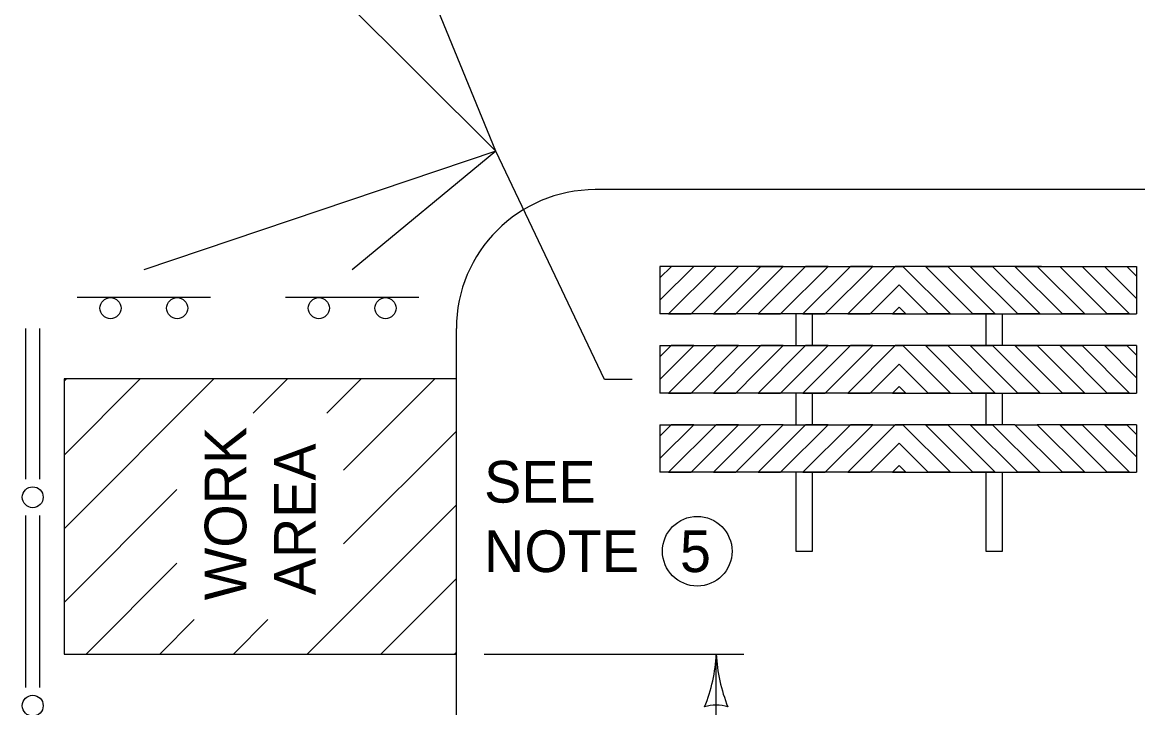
# Model space of a CAD drawing. Extents: x 49991.4 to 50021, y 49987.6 to 50011.4.
# Drawn here: x 50010.578 to 50012.184, y 49992.395 to 49993.381 of the extents above; entities that cross this region are included whole.
import ezdxf

# ---------------------------------------------------------------- set-up
doc = ezdxf.new("R2010")
doc.units = 0
for name, color, linetype in [('Level 1', 7, 'Continuous'), ('Level 2', 7, 'Continuous'), ('Level 3', 7, 'Continuous')]:
    doc.layers.add(name, color=color, linetype=linetype)

# ---------------------------------------------------------------- blocks, each defined once
blk = doc.blocks.new('ARR')
at = {"layer": 'Level 3'}
for centre, radius, start, end in [((1.53, 37.02), 37.05, 247.456, 267.6395), ((-21.37, 0), 9.13, 342.1388, 17.8612), ((1.92, -38.79), 38.83, 92.8273, 112.0772)]:
    blk.add_arc(centre, radius, start, end, dxfattribs=at)

msp = doc.modelspace()

# ---------------------------------------------------------------- linework, layer by layer
at = {"layer": 'Level 1'}
for p, q in [((50013.2032, 49993.1404), (50011.4032, 49993.1404)), ((50011.6213, 49993.03), (50011.4963, 49993.03)), ((50011.4963, 49992.9812), (50011.5451, 49993.03)), ((50011.4963, 49993.0134), (50011.5129, 49993.03)), ((50011.4963, 49993.03), (50011.4963, 49992.9616)), ((50011.5089, 49992.9616), (50011.5773, 49993.03)), ((50011.5411, 49992.9616), (50011.6095, 49993.03)), ((50011.5733, 49992.9616), (50011.6417, 49993.03)), ((50011.6417, 49993.03), (50011.6018, 49993.03)), ((50011.6055, 49992.9616), (50011.6739, 49993.03)), ((50011.6356, 49993.03), (50011.8408, 49993.03)), ((50011.6378, 49992.9616), (50011.7062, 49993.03)), ((50011.7062, 49993.03), (50011.6378, 49992.9616)), ((50011.67, 49992.9616), (50011.7384, 49993.03)), ((50011.67, 49992.9616), (50011.7384, 49993.03)), ((50011.7022, 49992.9616), (50011.7706, 49993.03)), ((50011.7706, 49993.03), (50011.7022, 49992.9616)), ((50011.7345, 49992.9616), (50011.8029, 49993.03)), ((50011.7345, 49992.9616), (50011.8029, 49993.03)), ((50011.7668, 49992.9616), (50011.8352, 49993.03)), ((50011.8352, 49993.03), (50011.7668, 49992.9616)), ((50011.8408, 49993.03), (50011.8352, 49993.03)), ((50012.046, 49993.03), (50011.8408, 49993.03)), ((50011.8408, 49993.03), (50011.8463, 49993.03)), ((50011.8463, 49993.03), (50011.9147, 49992.9616)), ((50011.9147, 49992.9616), (50011.8463, 49993.03)), ((50011.947, 49992.9616), (50011.8786, 49993.03)), ((50011.947, 49992.9616), (50011.8786, 49993.03)), ((50011.9793, 49992.9616), (50011.9109, 49993.03)), ((50011.9109, 49993.03), (50011.9793, 49992.9616)), ((50012.0115, 49992.9616), (50011.9431, 49993.03)), ((50012.0115, 49992.9616), (50011.9431, 49993.03)), ((50012.0437, 49992.9616), (50011.9753, 49993.03)), ((50011.9753, 49993.03), (50012.0437, 49992.9616)), ((50012.076, 49992.9616), (50012.0076, 49993.03)), ((50012.1082, 49992.9616), (50012.0398, 49993.03)), ((50012.0398, 49993.03), (50012.0797, 49993.03)), ((50012.0602, 49993.03), (50012.1828, 49993.03)), ((50012.1404, 49992.9616), (50012.072, 49993.03)), ((50012.1726, 49992.9616), (50012.1042, 49993.03)), ((50012.1828, 49992.9837), (50012.1364, 49993.03)), ((50012.1828, 49993.0159), (50012.1686, 49993.03)), ((50012.1828, 49993.03), (50012.1828, 49992.9616)), ((50011.799, 49992.9616), (50011.8408, 49993.0034)), ((50011.799, 49992.9616), (50011.8408, 49993.0034)), ((50011.8825, 49992.9616), (50011.8408, 49993.0034)), ((50011.8825, 49992.9616), (50011.8408, 49993.0034)), ((50010.7532, 49992.985), (50010.6572, 49992.985)), ((50010.8492, 49992.985), (50010.7532, 49992.985)), ((50011.0532, 49992.985), (50010.9572, 49992.985)), ((50011.1492, 49992.985), (50011.0532, 49992.985)), ((50011.8408, 49992.9616), (50011.6356, 49992.9616)), ((50011.6926, 49992.9161), (50011.6926, 49992.9616)), ((50011.8312, 49992.9616), (50011.8408, 49992.9711)), ((50011.8408, 49992.9711), (50011.8312, 49992.9616)), ((50011.8312, 49992.9616), (50011.8408, 49992.9616)), ((50011.8503, 49992.9616), (50011.8408, 49992.9711)), ((50011.8408, 49992.9711), (50011.8503, 49992.9616)), ((50011.8408, 49992.9616), (50012.046, 49992.9616)), ((50011.8503, 49992.9616), (50011.8408, 49992.9616)), ((50011.9662, 49992.9161), (50011.9662, 49992.9616)), ((50010.5832, 49992.7239), (50010.5832, 49992.9404)), ((50010.6032, 49992.7239), (50010.6032, 49992.9404)), ((50011.2032, 49988.1586), (50011.2032, 49992.9404)), ((50011.4963, 49992.8996), (50011.5127, 49992.9161)), ((50011.4963, 49992.8673), (50011.545, 49992.9161)), ((50011.4963, 49992.9161), (50011.6356, 49992.9161)), ((50011.4963, 49992.9161), (50011.4963, 49992.8477)), ((50011.5088, 49992.8477), (50011.5772, 49992.9161)), ((50011.5411, 49992.8477), (50011.6095, 49992.9161)), ((50011.5733, 49992.8477), (50011.6356, 49992.9099)), ((50011.6356, 49992.8777), (50011.6739, 49992.9161)), ((50011.6356, 49992.9161), (50011.8408, 49992.9161)), ((50011.6378, 49992.8477), (50011.7062, 49992.9161)), ((50011.7062, 49992.9161), (50011.6378, 49992.8477)), ((50011.67, 49992.8477), (50011.7384, 49992.9161)), ((50011.67, 49992.8477), (50011.7384, 49992.9161)), ((50011.7022, 49992.8477), (50011.7706, 49992.9161)), ((50011.7706, 49992.9161), (50011.7022, 49992.8477)), ((50011.7345, 49992.8477), (50011.8029, 49992.9161)), ((50011.7345, 49992.8477), (50011.8029, 49992.9161)), ((50011.7668, 49992.8477), (50011.8352, 49992.9161)), ((50011.8352, 49992.9161), (50011.7668, 49992.8477)), ((50011.8408, 49992.9161), (50011.8352, 49992.9161)), ((50012.046, 49992.9161), (50011.8408, 49992.9161)), ((50011.8408, 49992.9161), (50011.8463, 49992.9161)), ((50011.9147, 49992.8477), (50011.8463, 49992.9161)), ((50011.8463, 49992.9161), (50011.9147, 49992.8477)), ((50011.947, 49992.8477), (50011.8786, 49992.9161)), ((50011.947, 49992.8477), (50011.8786, 49992.9161)), ((50011.9793, 49992.8477), (50011.9109, 49992.9161)), ((50011.9109, 49992.9161), (50011.9793, 49992.8477)), ((50012.0115, 49992.8477), (50011.9431, 49992.9161)), ((50012.0115, 49992.8477), (50011.9431, 49992.9161)), ((50012.0437, 49992.8477), (50011.9753, 49992.9161)), ((50011.9753, 49992.9161), (50012.0437, 49992.8477)), ((50012.046, 49992.8777), (50012.0076, 49992.9161)), ((50012.1828, 49992.9161), (50012.046, 49992.9161)), ((50012.1082, 49992.8477), (50012.046, 49992.9099)), ((50012.1405, 49992.8477), (50012.0721, 49992.9161)), ((50012.1727, 49992.8477), (50012.1043, 49992.9161)), ((50012.1828, 49992.8698), (50012.1365, 49992.9161)), ((50012.1828, 49992.9021), (50012.1688, 49992.9161)), ((50012.1828, 49992.9161), (50012.1828, 49992.8477)), ((50011.6055, 49992.8477), (50011.6356, 49992.8777)), ((50011.799, 49992.8477), (50011.8408, 49992.8894)), ((50011.799, 49992.8477), (50011.8408, 49992.8894)), ((50011.8825, 49992.8477), (50011.8408, 49992.8894)), ((50011.8825, 49992.8477), (50011.8408, 49992.8894)), ((50012.076, 49992.8477), (50012.046, 49992.8777)), ((50011.2032, 49992.868), (50010.6384, 49992.868)), ((50010.6384, 49992.868), (50010.6384, 49992.4721)), ((50010.6384, 49992.8646), (50010.6418, 49992.868)), ((50010.6384, 49992.7585), (50010.7478, 49992.868)), ((50010.6384, 49992.6524), (50010.8539, 49992.868)), ((50010.9105, 49992.8185), (50010.96, 49992.868)), ((50011.0165, 49992.8185), (50011.066, 49992.868)), ((50011.0408, 49992.7367), (50011.1721, 49992.868)), ((50011.8408, 49992.8477), (50011.4963, 49992.8477)), ((50011.8312, 49992.8477), (50011.8408, 49992.8572)), ((50011.8408, 49992.8572), (50011.8312, 49992.8477)), ((50011.8312, 49992.8477), (50011.8408, 49992.8477)), ((50011.8503, 49992.8477), (50011.8408, 49992.8572)), ((50011.8408, 49992.8572), (50011.8503, 49992.8477)), ((50011.8408, 49992.8477), (50012.1828, 49992.8477)), ((50011.8503, 49992.8477), (50011.8408, 49992.8477)), ((50011.4963, 49992.7856), (50011.5127, 49992.8021)), ((50011.4963, 49992.7534), (50011.545, 49992.8021)), ((50011.4963, 49992.7534), (50011.545, 49992.8021)), ((50011.5127, 49992.8021), (50011.4963, 49992.7856)), ((50011.4963, 49992.8021), (50011.4963, 49992.7337)), ((50011.5088, 49992.7337), (50011.5772, 49992.8021)), ((50011.5772, 49992.8021), (50011.5088, 49992.7337)), ((50011.5411, 49992.7337), (50011.6095, 49992.8021)), ((50011.5411, 49992.7337), (50011.6095, 49992.8021)), ((50011.5733, 49992.7337), (50011.6417, 49992.8021)), ((50011.6417, 49992.8021), (50011.5733, 49992.7337)), ((50011.6055, 49992.7337), (50011.6739, 49992.8021)), ((50011.6055, 49992.7337), (50011.6739, 49992.8021)), ((50011.6378, 49992.7337), (50011.7062, 49992.8021)), ((50011.7062, 49992.8021), (50011.6378, 49992.7337)), ((50011.67, 49992.7337), (50011.7384, 49992.8021)), ((50011.67, 49992.7337), (50011.7384, 49992.8021)), ((50011.6739, 49992.8021), (50011.8408, 49992.8021)), ((50011.7022, 49992.7337), (50011.7706, 49992.8021)), ((50011.7706, 49992.8021), (50011.7022, 49992.7337)), ((50011.7345, 49992.7337), (50011.8029, 49992.8021)), ((50011.7345, 49992.7337), (50011.8029, 49992.8021)), ((50011.7668, 49992.7337), (50011.8352, 49992.8021)), ((50011.8352, 49992.8021), (50011.7668, 49992.7337)), ((50011.8408, 49992.8021), (50011.8352, 49992.8021)), ((50012.0076, 49992.8021), (50011.8408, 49992.8021)), ((50011.8408, 49992.8021), (50011.8463, 49992.8021)), ((50011.9147, 49992.7337), (50011.8463, 49992.8021)), ((50011.8463, 49992.8021), (50011.9147, 49992.7337)), ((50011.947, 49992.7337), (50011.8786, 49992.8021)), ((50011.947, 49992.7337), (50011.8786, 49992.8021)), ((50011.9793, 49992.7337), (50011.9109, 49992.8021)), ((50011.9109, 49992.8021), (50011.9793, 49992.7337)), ((50012.0115, 49992.7337), (50011.9431, 49992.8021)), ((50012.0115, 49992.7337), (50011.9431, 49992.8021)), ((50012.0437, 49992.7337), (50011.9753, 49992.8021)), ((50011.9753, 49992.8021), (50012.0437, 49992.7337)), ((50012.076, 49992.7337), (50012.0076, 49992.8021)), ((50012.076, 49992.7337), (50012.0076, 49992.8021)), ((50012.1082, 49992.7337), (50012.0398, 49992.8021)), ((50012.0398, 49992.8021), (50012.1082, 49992.7337)), ((50012.1405, 49992.7337), (50012.0721, 49992.8021)), ((50012.1405, 49992.7337), (50012.0721, 49992.8021)), ((50012.1727, 49992.7337), (50012.1043, 49992.8021)), ((50012.1043, 49992.8021), (50012.1727, 49992.7337)), ((50012.1828, 49992.7559), (50012.1365, 49992.8021)), ((50012.1828, 49992.7559), (50012.1365, 49992.8021)), ((50012.1828, 49992.7882), (50012.1688, 49992.8021)), ((50012.1688, 49992.8021), (50012.1828, 49992.7882)), ((50012.1828, 49992.8021), (50012.1828, 49992.7337)), ((50011.0408, 49992.6306), (50011.2032, 49992.793)), ((50011.799, 49992.7337), (50011.8408, 49992.7754)), ((50011.799, 49992.7337), (50011.8408, 49992.7754)), ((50011.8825, 49992.7337), (50011.8408, 49992.7754)), ((50011.8825, 49992.7337), (50011.8408, 49992.7754)), ((50011.8408, 49992.7337), (50011.4963, 49992.7337)), ((50011.8312, 49992.7337), (50011.8408, 49992.7432)), ((50011.8408, 49992.7432), (50011.8312, 49992.7337)), ((50011.8312, 49992.7337), (50011.8408, 49992.7337)), ((50011.8503, 49992.7337), (50011.8408, 49992.7432)), ((50011.8408, 49992.7432), (50011.8503, 49992.7337)), ((50011.8408, 49992.7337), (50012.1828, 49992.7337)), ((50011.8503, 49992.7337), (50011.8408, 49992.7337)), ((50010.6384, 49992.5464), (50010.8008, 49992.7088)), ((50010.9884, 49992.4721), (50011.2032, 49992.6869)), ((50010.5832, 49992.4239), (50010.5832, 49992.6715)), ((50010.6032, 49992.4239), (50010.6032, 49992.6715)), ((50010.6702, 49992.4721), (50010.8008, 49992.6027)), ((50011.0944, 49992.4721), (50011.2032, 49992.5809)), ((50010.7762, 49992.4721), (50010.8257, 49992.5216)), ((50010.8823, 49992.4721), (50010.9318, 49992.5216)), ((50010.6384, 49992.4721), (50011.2032, 49992.4721)), ((50011.2005, 49992.4721), (50011.2032, 49992.4748))]:
    msp.add_line(p, q, dxfattribs=at)
for points in [[(50011.4963, 49992.9812), (50011.5451, 49993.03)], [(50011.5451, 49993.03), (50011.5129, 49993.03), (50011.4963, 49993.0134)], [(50011.6095, 49993.03), (50011.6018, 49993.03), (50011.5773, 49993.03), (50011.5089, 49992.9616), (50011.5411, 49992.9616), (50011.6095, 49993.03)], [(50011.5733, 49992.9616), (50011.6055, 49992.9616), (50011.6739, 49993.03), (50011.6417, 49993.03), (50011.5733, 49992.9616)], [(50011.7384, 49993.03), (50011.7062, 49993.03)], [(50011.8825, 49992.9616), (50011.9147, 49992.9616), (50011.8463, 49993.03), (50011.8408, 49993.03), (50011.8352, 49993.03), (50011.7668, 49992.9616), (50011.799, 49992.9616), (50011.8408, 49993.0034), (50011.8825, 49992.9616)], [(50011.8029, 49993.03), (50011.7706, 49993.03)], [(50011.8786, 49993.03), (50011.9109, 49993.03)], [(50011.9431, 49993.03), (50011.9753, 49993.03)], [(50012.1082, 49992.9616), (50012.076, 49992.9616), (50012.0076, 49993.03), (50012.0398, 49993.03), (50012.1082, 49992.9616)], [(50012.072, 49993.03), (50012.0797, 49993.03), (50012.1042, 49993.03), (50012.1726, 49992.9616), (50012.1404, 49992.9616), (50012.072, 49993.03)], [(50012.1828, 49992.9837), (50012.1364, 49993.03)], [(50012.1364, 49993.03), (50012.1686, 49993.03), (50012.1828, 49993.0159)], [(50011.4963, 49993.0134), (50011.4963, 49992.9812)], [(50012.1828, 49993.0159), (50012.1828, 49992.9837)], [(50011.6356, 49992.9616), (50011.4963, 49992.9616)], [(50011.6378, 49992.9616), (50011.67, 49992.9616)], [(50011.7022, 49992.9616), (50011.7345, 49992.9616)], [(50011.7154, 49992.9616), (50011.7154, 49992.9161)], [(50011.7668, 49992.9616), (50011.799, 49992.9616)], [(50011.8312, 49992.9616), (50011.8408, 49992.9616), (50011.8503, 49992.9616), (50011.8408, 49992.9711), (50011.8312, 49992.9616)], [(50011.9147, 49992.9616), (50011.8825, 49992.9616)], [(50011.9793, 49992.9616), (50011.947, 49992.9616)], [(50011.989, 49992.9616), (50011.989, 49992.9161)], [(50012.0437, 49992.9616), (50012.0115, 49992.9616)], [(50012.046, 49992.9616), (50012.1828, 49992.9616)], [(50011.4963, 49992.8673), (50011.545, 49992.9161)], [(50011.545, 49992.9161), (50011.5127, 49992.9161), (50011.4963, 49992.8996)], [(50011.6095, 49992.9161), (50011.5772, 49992.9161), (50011.5088, 49992.8477), (50011.5411, 49992.8477), (50011.6095, 49992.9161)], [(50011.5733, 49992.8477), (50011.6055, 49992.8477), (50011.6356, 49992.8777), (50011.6739, 49992.9161), (50011.647, 49992.9161), (50011.6417, 49992.9161), (50011.6356, 49992.9099), (50011.5733, 49992.8477)], [(50011.7384, 49992.9161), (50011.7062, 49992.9161)], [(50011.8825, 49992.8477), (50011.9147, 49992.8477), (50011.8463, 49992.9161), (50011.8408, 49992.9161), (50011.8352, 49992.9161), (50011.7668, 49992.8477), (50011.799, 49992.8477), (50011.8408, 49992.8894), (50011.8825, 49992.8477)], [(50011.8029, 49992.9161), (50011.7706, 49992.9161)], [(50011.8786, 49992.9161), (50011.9109, 49992.9161)], [(50011.9431, 49992.9161), (50011.9753, 49992.9161)], [(50012.1082, 49992.8477), (50012.076, 49992.8477), (50012.046, 49992.8777), (50012.0076, 49992.9161), (50012.0346, 49992.9161), (50012.0398, 49992.9161), (50012.046, 49992.9099), (50012.1082, 49992.8477)], [(50012.0721, 49992.9161), (50012.1043, 49992.9161), (50012.1727, 49992.8477), (50012.1405, 49992.8477), (50012.0721, 49992.9161)], [(50012.1828, 49992.8698), (50012.1365, 49992.9161)], [(50012.1365, 49992.9161), (50012.1688, 49992.9161), (50012.1828, 49992.9021)], [(50011.4963, 49992.8996), (50011.4963, 49992.8673)], [(50012.1828, 49992.9021), (50012.1828, 49992.8698)], [(50011.6378, 49992.8477), (50011.67, 49992.8477)], [(50011.6926, 49992.8021), (50011.6926, 49992.8477)], [(50011.7022, 49992.8477), (50011.7345, 49992.8477)], [(50011.7154, 49992.8477), (50011.7154, 49992.8021)], [(50011.7668, 49992.8477), (50011.799, 49992.8477)], [(50011.8312, 49992.8477), (50011.8408, 49992.8477), (50011.8503, 49992.8477), (50011.8408, 49992.8572), (50011.8312, 49992.8477)], [(50011.9147, 49992.8477), (50011.8825, 49992.8477)], [(50011.9793, 49992.8477), (50011.947, 49992.8477)], [(50011.9662, 49992.8021), (50011.9662, 49992.8477)], [(50011.989, 49992.8477), (50011.989, 49992.8021)], [(50012.0437, 49992.8477), (50012.0115, 49992.8477)], [(50011.4963, 49992.8021), (50011.6417, 49992.8021)], [(50011.545, 49992.8021), (50011.5127, 49992.8021)], [(50011.6095, 49992.8021), (50011.5772, 49992.8021)], [(50011.6739, 49992.8021), (50011.6417, 49992.8021)], [(50011.7384, 49992.8021), (50011.7062, 49992.8021)], [(50011.8825, 49992.7337), (50011.9147, 49992.7337), (50011.8463, 49992.8021), (50011.8408, 49992.8021), (50011.8352, 49992.8021), (50011.7668, 49992.7337), (50011.799, 49992.7337), (50011.8408, 49992.7754), (50011.8825, 49992.7337)], [(50011.8029, 49992.8021), (50011.7706, 49992.8021)], [(50011.8786, 49992.8021), (50011.9109, 49992.8021)], [(50011.9431, 49992.8021), (50011.9753, 49992.8021)], [(50012.0076, 49992.8021), (50012.0398, 49992.8021)], [(50012.1828, 49992.8021), (50012.0398, 49992.8021)], [(50012.0721, 49992.8021), (50012.1043, 49992.8021)], [(50012.1365, 49992.8021), (50012.1688, 49992.8021)], [(50011.4963, 49992.7856), (50011.4963, 49992.7534)], [(50012.1828, 49992.7882), (50012.1828, 49992.7559)], [(50011.5088, 49992.7337), (50011.5411, 49992.7337)], [(50011.5733, 49992.7337), (50011.6055, 49992.7337)], [(50011.6378, 49992.7337), (50011.67, 49992.7337)], [(50011.7154, 49992.7336), (50011.7154, 49992.6196), (50011.6926, 49992.6196), (50011.6926, 49992.7336)], [(50011.7022, 49992.7337), (50011.7345, 49992.7337)], [(50011.7668, 49992.7337), (50011.799, 49992.7337)], [(50011.8312, 49992.7337), (50011.8408, 49992.7337), (50011.8503, 49992.7337), (50011.8408, 49992.7432), (50011.8312, 49992.7337)], [(50011.9147, 49992.7337), (50011.8825, 49992.7337)], [(50011.9793, 49992.7337), (50011.947, 49992.7337)], [(50011.989, 49992.7336), (50011.989, 49992.6196), (50011.9662, 49992.6196), (50011.9662, 49992.7336)], [(50012.0437, 49992.7337), (50012.0115, 49992.7337)], [(50012.1082, 49992.7337), (50012.076, 49992.7337)], [(50012.1727, 49992.7337), (50012.1405, 49992.7337)]]:
    msp.add_lwpolyline(points, dxfattribs=at)
for centre, radius in [((50010.7052, 49992.9698), 0.0152), ((50010.8012, 49992.9698), 0.0152), ((50011.0052, 49992.9698), 0.0152), ((50011.1012, 49992.9698), 0.0152), ((50010.5932, 49992.6977), 0.015), ((50010.5932, 49992.3977), 0.015)]:
    msp.add_circle(centre, radius, dxfattribs=at)
msp.add_arc((50011.4032, 49992.9404), 0.2, 90, 180, dxfattribs=at)
at = {"layer": 'Level 2'}
msp.add_circle((50011.5501, 49992.62), 0.0501, dxfattribs=at)
at = {"layer": 'Level 3'}
for p, q in [((50011.2601, 49993.1959), (50010.7532, 49993.7005)), ((50011.2601, 49993.1959), (50011.0532, 49993.7005)), ((50011.2601, 49993.1959), (50010.7532, 49993.025)), ((50011.2601, 49993.1959), (50011.0532, 49993.025)), ((50011.4163, 49992.8673), (50011.2601, 49993.1959)), ((50011.4563, 49992.8673), (50011.4163, 49992.8673)), ((50011.2432, 49992.4721), (50011.6174, 49992.4721)), ((50011.5774, 49992.0977), (50011.5774, 49992.4721))]:
    msp.add_line(p, q, dxfattribs=at)

# ---------------------------------------------------------------- block references
at = {"layer": 'Level 3', "xscale": 0.006, "yscale": 0.006, "rotation": 90}
msp.add_blockref('ARR', (50011.5774, 49992.4721), dxfattribs=at)

# ---------------------------------------------------------------- texts
at = {"layer": 'Level 2'}
for s, p in [('WORK', (50010.9008, 49992.5494)), ('AREA', (50011.0008, 49992.5567))]:
    msp.add_text(s, height=0.06, rotation=90, dxfattribs=at).set_placement(p)
for s, p in [('SEE', (50011.2432, 49992.69)), ('NOTE', (50011.2432, 49992.59)), ('5', (50011.5252, 49992.59))]:
    msp.add_text(s, height=0.06, dxfattribs=at).set_placement(p)

doc.saveas('drawing.dxf')
